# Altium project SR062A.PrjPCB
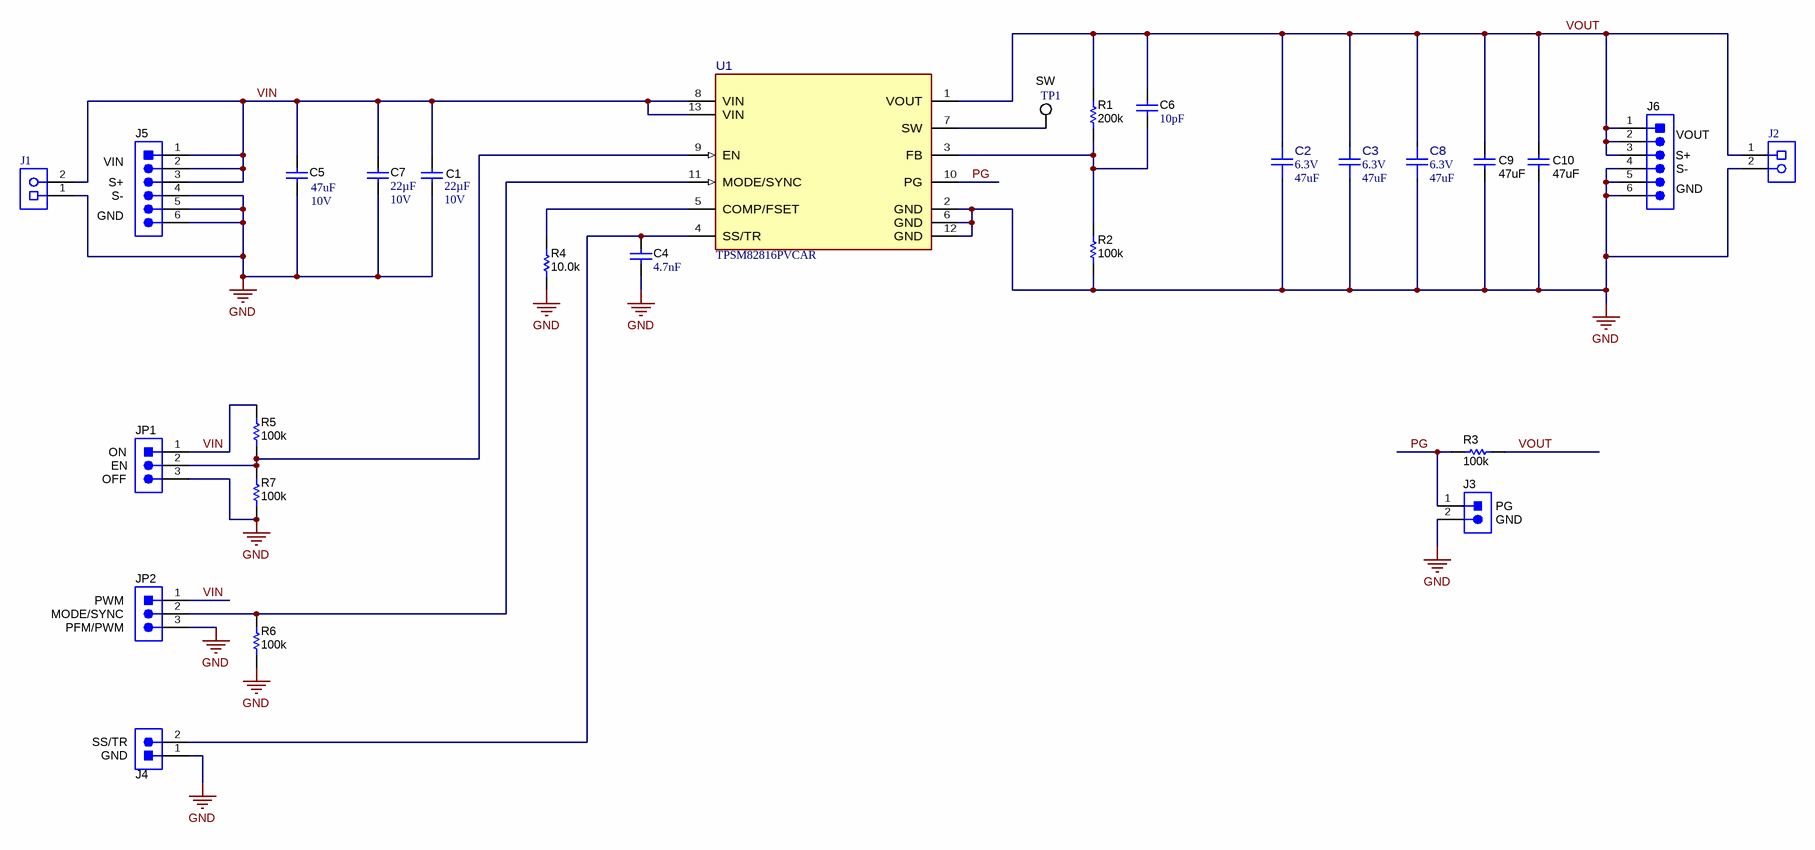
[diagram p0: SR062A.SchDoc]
TID: N/A; SCH_Rev: A; PRJ_Title: TPSM82816PEVM-062; PRJ_Number: SR062; PRJ_Customer: Public Release; PCB_Rev: A; CopyrightYear: 2024
2 sheets, 39 parts. Net scope: global (net labels, ports and power ports of the same name join across sheets).
Board file: SR062A.PcbDoc
Sheets:
  SR062A.SchDoc
  SR062A_Hardware.SchDoc

## Sheet SR062A.SchDoc
size 431 x 279 mm; Date: Not shown in title block; ApprovedBy: Not shown in title block; CheckedBy: Not shown in title block; Author: Not shown in title block; CompanyName: Not shown in title block; Engineer: Not shown in title block; Organization: Not shown in title block; Address1: Not shown in title block; Address2: Not shown in title block; Address3: Not shown in title block; Address4: Not shown in title block; DocumentNumber: 1; Revision: Use project parameter SCH_Rev; SheetNumber: 1; SheetTotal: 2; PageSetup: Record=PageOptions¦CenterHorizontal=True¦CenterVertical=True¦PrintScale=1.00¦XCorrection=1.00¦YCorrection=1.00¦PrintKind=0¦BorderSize=5000000¦LeftOffset=0¦BottomOffset=0¦Orientation=2¦PaperLength=1000¦PaperWidth=1000¦Scale=100¦PaperSource=15¦PrintQuality=600¦MediaType=1¦DitherType=10¦PaperKind=Letter¦PrintScaleMode=1

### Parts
C1  Cap_F: 22µF  VDC_V: 10V  [0805_HV1]  (hidden comment: GRM21BZ71A226ME15L)
C2  VDC_V: 6.3V  ValueDisplayed: 47uF  [FP-GRM21BC80J476ME01L_0805-MFG]  (hidden comment: GRM21BC80J476ME01L)
C3  VDC_V: 6.3V  ValueDisplayed: 47uF  [FP-GRM21BC80J476ME01L_0805-MFG]  (hidden comment: GRM21BC80J476ME01L)
C4  Cap_F: 4.7nF  [0603S]  (hidden comment: 885012206087)
C5  VDC_V: 10V  ValueDisplayed: 47uF  [1210_270]  (hidden comment: GRM32ER71A476ME15L)
C6  ValueDisplayed: 10pF  [0603S]  (hidden comment: 885012006073)
C7  Cap_F: 22µF  VDC_V: 10V  [0805_HV1]  (hidden comment: GRM21BZ71A226ME15L)
C8  VDC_V: 6.3V  ValueDisplayed: 47uF  [FP-GRM21BC80J476ME01L_0805-MFG]  (hidden comment: GRM21BC80J476ME01L)
C9  ValueDisplayed: 47uF  [1210_270]  (hidden comment: GRM32ED71A476ME15L)
C10  ValueDisplayed: 47uF  [1210_270]  (hidden comment: GRM32ED71A476ME15L)
J1  691214110002S  [FP-691214110002S_HDR2-MFG]  (value not drawn)
J2  691214110002S  [FP-691214110002S_HDR2-MFG]  (value not drawn)
J3  61300211121  [WURTH_61300211121]  (value not drawn)
J4  61300211121  [WURTH_61300211121]  (value not drawn)
J5  61300611121  [WURTH_61300611121]  (value not drawn)
J6  61300611121  [WURTH_61300611121]  (value not drawn)
JP1  61300311121  [WURTH_61300311121]  (value not drawn)
JP2  61300311121  [WURTH_61300311121]  (value not drawn)
R1  ValueDisplayed: 200k  [0603S]  (hidden comment: RC0603FR-07200KL)
R2  ValueDisplayed: 100k  [0603S]  (hidden comment: RC0603FR-07100KL)
R3  ValueDisplayed: 100k  [0603]  (hidden comment: RC0603FR-07100KL)
R4  ValueDisplayed: 10.0k  [0603S]  (hidden comment: ERJ-3EKF1002V)
R5  ValueDisplayed: 100k  [0603]  (hidden comment: RC0603FR-07100KL)
R6  ValueDisplayed: 100k  [0603]  (hidden comment: RC0603FR-07100KL)
R7  ValueDisplayed: 100k  [0603]  (hidden comment: RC0603FR-07100KL)
TP1  5002  [Keystone5002]  (value not drawn)
U1  TPSM82816PVCAR  [VCA0013A-MFG]

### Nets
GND: C1.2 C2.1 C3.1 C4.2 C5.2 C7.2 C8.1 C9.2 C10.2 J1.1 J2.2 J3.2 J4.1 J5.4 J5.5 J5.6 J6.4 J6.5 J6.6 JP1.3 JP2.3 R2.1 R4.1 R6.1 R7.1 U1.2(GND) U1.6(GND) U1.12(GND)
PG: J3.1 R3.1 U1.10(PG)
VIN: C1.1 C5.1 C7.1 J1.2 J5.1 J5.2 J5.3 JP1.1 JP2.1 R5.2 U1.8(VIN) U1.13(VIN)
VOUT: C2.2 C3.2 C6.1 C8.2 C9.1 C10.1 J2.1 J6.1 J6.2 J6.3 R1.2 R3.2 U1.1(VOUT)
NetC4_1: C4.1 J4.2 U1.4(SS/TR)
NetC6_2: C6.2 R1.1 R2.2 U1.3(FB)
NetJP1_2: JP1.2 R5.1 R7.2 U1.9(EN)
NetJP2_2: JP2.2 R6.2 U1.11(MODE/SYNC)
NetR4_2: R4.2 U1.5(COMP/FSET)
NetTP1_1: TP1.1 U1.7(SW)

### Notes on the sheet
- SW
- (near J6) VOUT
- VIN
- (near J5) S+
- (near J5) S-
- (near J6) S-
- (near J6) S+
- (near J6) GND
- GND
- (near JP1) ON
- (near JP1) EN
- (near JP1) OFF
- PG
- (near J3) GND
- (near JP2) PWM
- (near JP2) MODE/SYNC
- (near JP2) PFM/PWM
- (near J4) SS/TR
- (near J4) GND

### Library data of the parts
C1 C7 = CMP-0008377-2: CAP, CERM, 22 uF, 10 V, +/- 20%, X7R, 0805; Manufacturer: MuRata; SizeY_mm: 1.25; Cap_Case: 0805; SizeArea_mm2: 2.5; AEC Qualified: N; AEC Category: Q200; ValueDisplayed: 22uF; TaMin_C: -55°C; SizeAreaWB_mm2: 6.75; Value1: Unknown; U/M: EA; Value: 22uF; TaMax_C: 125°C; SizeZ_mm: 1.45; SizeX_mm: 2
C2 C3 C8 = CMP-0097404-2: Chip Multilayer Ceramic Capacitors for General Purpose, 47μF ±20%, X6S(EIA), ±22.0%, 6.3Vdc, 0805 (2012M); Manufacturer: Murata; SizeZ_mm: 1.45mm; AEC Qualified: No; TempCo: 22%
C4 = CMP-0006835-4: CAP, CERM, 4700 pF, 50 V, +/- 10%, X7R, 0603; Manufacturer: Wurth Elektronik; TaMin_C: -55°C; Polarized: N; SizeAreaWB_mm2: 4.68; Value1: Unknown; U/M: EA; Value: 4700pF; TaMax_C: 125°C; SizeZ_mm: 1; SizeX_mm: 1.6; SizeY_mm: 0.8; Cap_Case: 0603; Value2: 50V; SizeArea_mm2: 1.28; AEC Category: Q200
C5 = CMP-0009221-2: CAP, CERM, 47 uF, 10 V, +/- 20%, X7R, 1210; Manufacturer: MuRata; TaMin_C: -55°C; Polarized: N; SizeAreaWB_mm2: 14.7; Value1: Unknown; U/M: EA; Value: 47uF; TaMax_C: 125°C; SizeZ_mm: 2.7; SizeX_mm: 3.2; SizeY_mm: 2.5; Cap_Case: 1210; SizeArea_mm2: 8; Cap_F: 47µF; AEC Category: Q200
C6 = CMP-0078152-1: CAP, CERM, 10 pF, 100 V,+/- 5%, C0G/NP0, 0603; Manufacturer: Wurth Elektronik; TaMin_C: -55°C; Polarized: N; SizeAreaWB_mm2: 4.68; U/M: EA; Value: 10pF; TaMax_C: 125°C; SizeZ_mm: 1; SizeX_mm: 1.6; SizeY_mm: 0.8; Cap_Case: 0603; Value2: 100V; SizeArea_mm2: 1.28; AEC Category: Q200
C9 C10 = CMP-0086480-2: 47µF ±20% 10V Ceramic Capacitor X7T 1210 (3225 Metric); Manufacturer: Murata; AEC Qualified: No; SizeZ_mm: 2.7mm; TempCo: +22-33%
J1 J2 = CMP-0093089-2: 2 Position Wire to Board Terminal Block Horizontal with Board 0.138" (3.50mm) Through Hole; Manufacturer: Wurth; Voltage_V: 300V; ContactFinish: Tin,Nickel; Current_A: 10A; Row_Count: 1; SizeZ_mm: 9.2mm; Is Female: yes; Max Wire Gauge: 16; AEC Qualified: No; DUT-Pitch_mm: 3.5mm; Min Wire Gauge: 30; Conn Gender: Female
J3 J4 = CMP-0054794-2: Header, 2.54 mm, 2x1, Gold, TH; Manufacturer: Wurth Elektronik; Pitch_mm: 2.54; Gender: Male; Cert_UL: Y; Green_REACh: Passed; Shrouded: N; Green_Lifecycle: Active; Row_Count: 1
J5 J6 = CMP-0054801-2: Header, 2.54 mm, 6x1, Gold, TH; Manufacturer: Wurth Elektronik; Pitch_mm: 2.54; Gender: Male; Shrouded: N; Row_Count: 1; Cert_UL: Y
JP1 JP2 = CMP-0054796-4: Header, 2.54 mm, 3x1, Gold, TH; Manufacturer: Wurth Elektronik; Green_REACh: Passed; Green_Lifecycle: Active; CT: FALSE; CNHeader: TRUE
R1 = CMP-0022901-4: RES, 200 k, 1%, 0.1 W, 0603; Manufacturer: Yageo; Power_W: 100mW; TempCo: 100 ppm/C; Value: 200k; EIA_Code: E96; SizeX_mm: 1.6; SizeY_mm: 0.8; SizeZ_mm: 1; Value2: 0.1W; CompType: Resistor; AEC Qualified: N; VDC_V: 75V; AEC Category: Q200; SizeArea_mm2: 1.28; SizeAreaWB_mm2: 4.68
R2 R3 R5-R7 = CMP-0022735-5: RES, 100 k, 1%, 0.1 W, 0603; Manufacturer: Yageo; Power_W: 100mW; TempCo: 100 ppm/C; Value: 100k; EIA_Code: E96; SizeX_mm: 1.6; SizeY_mm: 0.8; SizeZ_mm: 1; Value2: 0.1W; SizeArea_mm2: 1.28; CompType: Resistor; AEC Qualified: N; VDC_V: 75V; AEC Category: Q200; SizeAreaWB_mm2: 4.68
R4 = CMP-0022684-3: RES, 10.0 k, 1%, 0.1 W, 0603; Manufacturer: Panasonic; Power_W: 100mW; TempCo: 100 ppm/C; Value_Code: 10k0; U/M: EA; Value: 10.0k; EIA_Code: E96; Res_ohm: 10k; SizeX_mm: 1.6; SizeY_mm: 0.8; SizeZ_mm: 1; Value2: 0.1W; SizeArea_mm2: 1.28; VDC_V: 75V; AEC Category: Q200
TP1 = CMP-0055139-2: Test Point, Miniature, White, TH; Manufacturer: Keystone Electronics; ContactFinish: Silver; Green_REACh: Passed; CT: TRUE; Green_Lifecycle: Active; CNHeader: FALSE
U1 = CMP-0120848-2: 2.7-V to 6-V Input 6-A Step-Down Power Module with Integrated Inductor and Frequency Synchronization; Manufacturer: Texas Instruments; SizeZ_mm: 2mm; AEC Qualified: No; Max Duty Cycle: 100%; Max Supply Voltage: 6V; Min Supply Voltage: 2.7V; Nominal Supply Current: 18uA; Number Of Outputs: 1; Output Type: AdjustableProgrammable; Output Voltage: 0.6-5.5V; Switching Frequency: 1.8-4MHz; Switching Topology: Buck; TJmax_C: +125°C; AEC Category: Q200; CompType: IC

## Sheet SR062A_Hardware.SchDoc
size 431 x 279 mm; Date: Not shown in title block; ApprovedBy: Not shown in title block; CheckedBy: Not shown in title block; Author: Not shown in title block; CompanyName: Not shown in title block; Engineer: Not shown in title block; Organization: Not shown in title block; Address1: Not shown in title block; Address2: Not shown in title block; Address3: Not shown in title block; Address4: Not shown in title block; DocumentNumber: 2; Revision: Use project parameter SCH_Rev; SheetNumber: 2; SheetTotal: 2; PageSetup: Record=PageOptions¦CenterHorizontal=True¦CenterVertical=True¦PrintScale=1.00¦XCorrection=1.00¦YCorrection=1.00¦PrintKind=0¦BorderSize=5000000¦LeftOffset=0¦BottomOffset=0¦Orientation=2¦PaperLength=1000¦PaperWidth=1000¦Scale=100¦PaperSource=15¦PrintQuality=600¦MediaType=1¦DitherType=10¦PaperKind=Letter¦PrintScaleMode=1
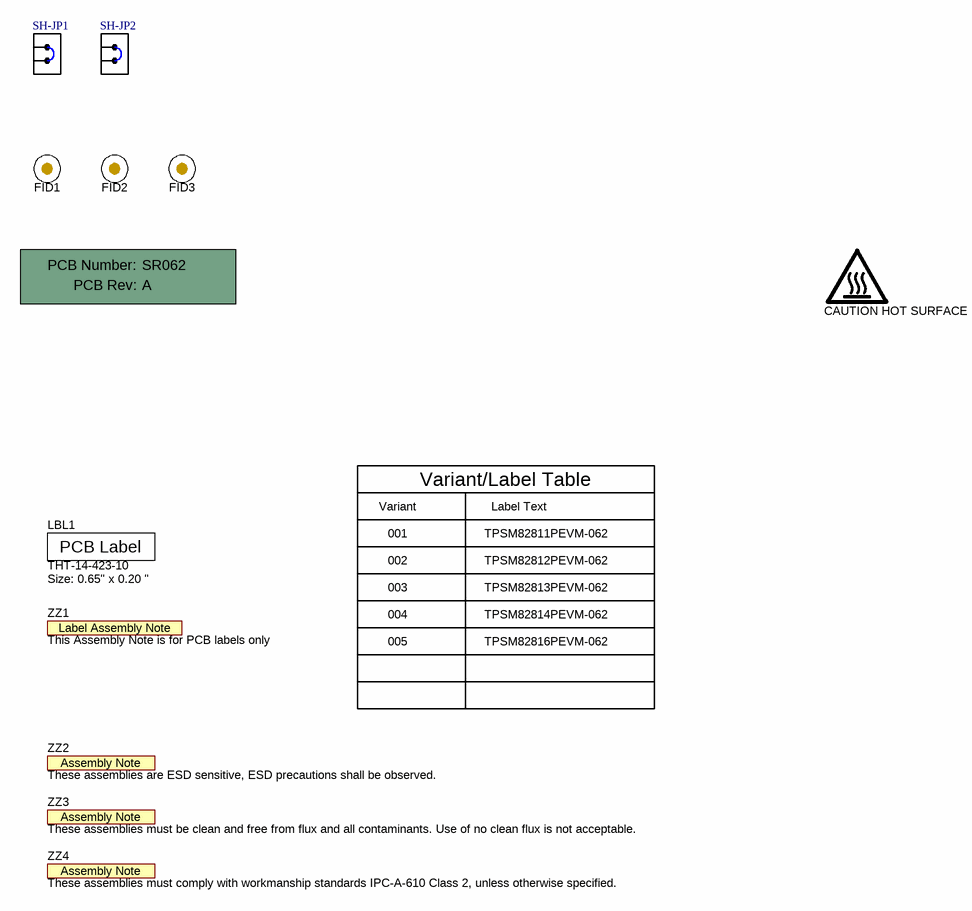
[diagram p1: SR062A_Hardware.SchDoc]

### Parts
!PCB1  Printed Circuit Board  (value not drawn)  (mechanical)
FID1  Fiducial  [Fiducial10-20]  (value not drawn)
FID2  Fiducial  [Fiducial10-20]  (value not drawn)
FID3  Fiducial  [Fiducial10-20]  (value not drawn)
LBL1  THT-14-423-10  Note: Size: 0.65" x 0.20 "  [Label_650x200]
Logo5  CAUTION HOT SURFACE  [IEC_HotSurface_Small]  (no BOM)
SH-JP1  60900213421  [Wurth_60900213421]  (value not drawn)
SH-JP2  60900213421  [Wurth_60900213421]  (value not drawn)
ZZ1  This Assembly Note is for PCB labels only  [AssemblyNoteLabel]  (no BOM)
ZZ2  These assemblies are ESD sensitive, ESD precautions shall be observed.  [AssemblyNote]  (no BOM)
ZZ3  These assemblies must be clean and free from flux and all contaminants. Use of no clean flux is not acceptable.  [AssemblyNote]  (no BOM)
ZZ4  These assemblies must comply with workmanship standards IPC-A-610 Class 2, unless otherwise specified.  [AssemblyNote]  (no BOM)

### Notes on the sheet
- Variant/Label Table
- Variant
- 001
- Label Text
- TPSM82811PEVM-062
- 002
- 003
- 004
- TPSM82814PEVM-062
- TPSM82813PEVM-062
- TPSM82812PEVM-062
- 005
- TPSM82816PEVM-062

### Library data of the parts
!PCB1 = CMP-0003618-2: Manufacturer: Any; PartNumber: SR062
FID1-FID3 = CMP-0077181-1: Fiducial mark.  There is nothing to buy or mount.
LBL1 = CMP-0003625-1: Thermal Transfer Printable Labels, 0.650" W x 0.200" H - 10,000 per roll; Manufacturer: Brady; CompType: Label
Logo5 = CMP-0074837-2: IEC 61010-1 Hot Surface Warning; Manufacturer: Texas Instruments; SymbolCreator: a0412235; AEC Category: Q200; CompType: IC
SH-JP1 SH-JP2 = CMP-0003761-2: Shunt, 2.54mm, Gold, Black; Manufacturer: Wurth Elektronik
ZZ1 = CMP-0003616-3
ZZ2 = CMP-0077236-1
ZZ3 = CMP-0077237-1
ZZ4 = CMP-0077238-1

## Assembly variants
001: not fitted C7 C8 C9 C10 FID1 FID2 FID3 J1 J2 R7 TP1; alternate parts U1 -> CMP-0121579-1
002: not fitted C7 C8 C9 C10 FID1 FID2 FID3 J1 J2 R7 TP1; alternate parts U1 -> CMP-0121580-1
003: not fitted C7 C8 C9 C10 FID1 FID2 FID3 J1 J2 R7 TP1; alternate parts U1 -> CMP-0121581-1
004: not fitted C7 C8 C9 C10 FID1 FID2 FID3 R7 TP1; alternate parts U1 -> CMP-0121361-1
005: not fitted C7 C8 C9 C10 FID1 FID2 FID3 R7 TP1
